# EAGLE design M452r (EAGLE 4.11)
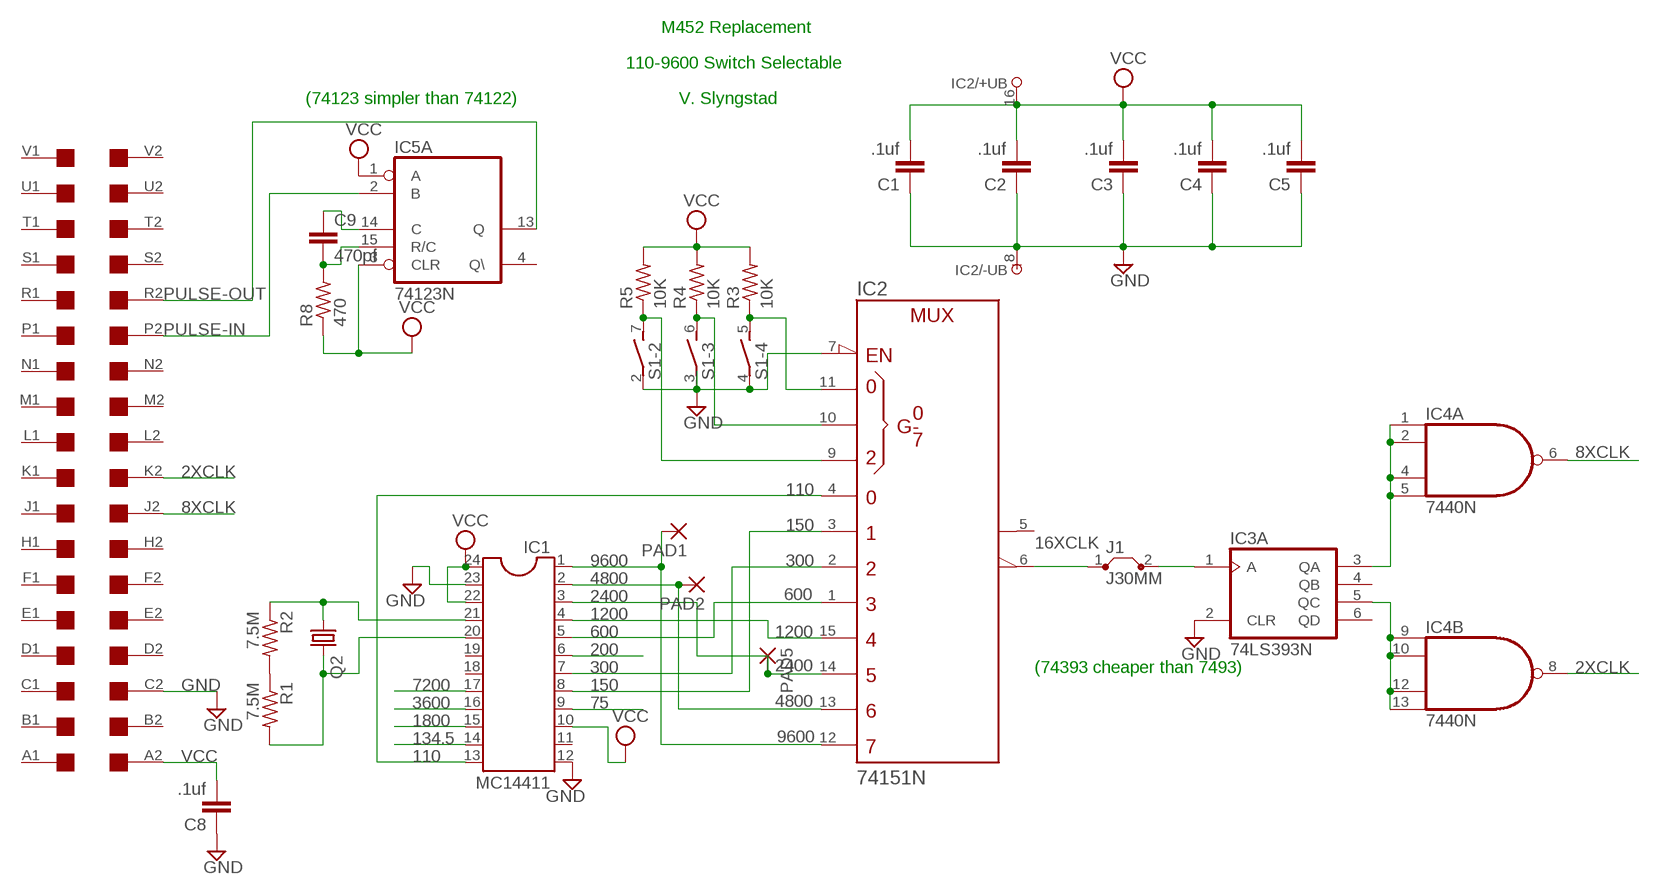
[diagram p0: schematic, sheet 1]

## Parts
C1  .1uf  C-EU050-025X075  [C050-025X075]
C2  .1uf  C-EU050-025X075  [C050-025X075]
C3  .1uf  C-EU050-025X075  [C050-025X075]
C4  .1uf  C-EU050-025X075  [C050-025X075]
C5  .1uf  C-EU050-025X075  [C050-025X075]
C8  .1uf  C-EU050-025X075  [C050-025X075]
C9  470pf  C-EU050-025X075  [C050-025X075]
IC1  MC14411  DIL24-6  [DIL24-6]
IC2  74151N  [DIL16]
IC3  74LS393N  [DIL14]
IC4  7440N  74S20N  [DIL14]
IC5  74123N  [DIL16]
J1  J30MM  [30]
PAD1  1,6/0,8  [1,6/0,8]
PAD2  1,6/0,8  [1,6/0,8]
PAD5  1,6/0,8  [1,6/0,8]
Q2  CRYTALHC49U-H  [HC49U-H]
R1  7.5M  R-US_0204/7  [0204/7]
R2  7.5M  R-US_0204/7  [0204/7]
R3  10K  R-US_0204/7  [0204/7]
R4  10K  R-US_0204/7  [0204/7]
R5  10K  R-US_0204/7  [0204/7]
R8  470  R-US_0204/7  [0204/7]
S1  DIP04S  [DIP04S]
U$1  DEC-FLIPCHIP  [DEC-FLIPCHIP]

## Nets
2XCLK: IC4.8(B:O) U$1.K2
8XCLK: IC4.6(A:O) U$1.J2
16XCLK: IC2.6(W) J1.1
75: IC1.9
110: IC1.13 IC2.4(D0)
134.5: IC1.14
150: IC1.8 IC2.3(D1)
200: IC1.6
300: IC1.7 IC2.2(D2)
600: IC1.5 IC2.1(D3)
1200: IC1.4 IC2.15(D4)
1800: IC1.15
2400: IC1.3 IC2.14(D5) PAD5.1(P)
3600: IC1.16
4800: IC1.2 IC2.13(D6) PAD2.1(P)
7200: IC1.17
9600: IC1.1 IC2.12(D7) PAD1.1(P)
GND: C1.1 C2.1 C3.1 C4.1 C5.1 C8.1 IC1.12 IC1.23 IC2.7(G\) IC2.8(-UB) IC3.2(A:CLR) S1.2 S1.3 S1.4 U$1.C2
N$1: IC1.20 Q2.2 R1.2
N$2: IC2.9(C) R5.1 S1.7
N$3: R1.1 R2.2
N$4: IC3.1(A:A) J1.2
N$10: IC3.5(A:QC) IC4.9(B:I0) IC4.10(B:I1) IC4.12(B:I2) IC4.13(B:I3)
N$12: IC3.3(A:QA) IC4.1(A:I0) IC4.2(A:I1) IC4.4(A:I2) IC4.5(A:I3)
N$17: IC2.11(A) R3.1 S1.5
N$18: IC1.21 Q2.1 R2.1
N$20: IC2.10(B) R4.1 S1.6
N$21: C9.2 IC5.15(A:R/C) R8.2
N$22: C9.1 IC5.14(A:C)
PULSE-IN: IC5.2(A:B) U$1.P2
PULSE-OUT: IC5.13(A:Q) U$1.R2
VCC: C1.2 C2.2 C3.2 C4.2 C5.2 C8.2 IC1.10 IC1.22 IC1.24 IC2.16(+UB) IC5.1(A:A) IC5.3(A:CLR) R3.2 R4.2 R5.2 R8.1 U$1.A2
Unconnected: IC1.11 IC1.18 IC1.19 IC2.5(Y) IC3.4(A:QB) IC3.6(A:QD) IC3.8(B:QD) IC3.9(B:QC) IC3.10(B:QB) IC3.11(B:QA) IC3.12(B:CLR) IC3.13(B:A) IC5.4(A:Q\) IC5.5(B:Q) IC5.6(B:C) IC5.7(B:R/C) IC5.9(B:A) IC5.10(B:B) IC5.11(B:CLR) IC5.12(B:Q\) S1.1 S1.8 U$1.A1 U$1.B1 U$1.B2 U$1.C1 U$1.D1 U$1.D2 U$1.E1 U$1.E2 U$1.F1 U$1.F2 U$1.H1 U$1.H2 U$1.J1 U$1.K1 U$1.L1 U$1.L2 U$1.M1 U$1.M2 U$1.N1 U$1.N2 U$1.P1 U$1.R1 U$1.S1 U$1.S2 U$1.T1 U$1.T2 U$1.U1 U$1.U2 U$1.V1 U$1.V2

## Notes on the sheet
- M452 Replacement
- 110-9600 Switch Selectable
- (74123 simpler than 74122) | V. Slyngstad
- (74393 cheaper than 7493)

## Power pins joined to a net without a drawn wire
GND: IC3.7(P:GND) IC4.7(P:GND) IC5.8(P:GND)
VCC: IC3.14(P:VCC) IC4.14(P:VCC) IC5.16(P:VCC)

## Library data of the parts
C1-C5 C8 C9 = rcl:C-EU: CAPACITOR, European symbol
IC1 = ic-package:DIL24: Dual In Line
IC2 = 74ttl-din:74*151: Data SELECTOR/MULTIPLEXER
IC3 = 74xx-us:74*393: Dual 4-bit decade and binary COUNTER
IC4 = 74xx-us:74*20: Dual 4-input NAND gate
IC5 = 74xx-us:74*123: Retriggerable monostable MULTIVIBRATOR
J1 = jumper:J: Bridge
PAD1 PAD2 PAD5 = wirepad:1,6/0,8: THROUGH-HOLE PAD
Q2 = crystal:CRYTAL: CRYSTAL
R1-R5 R8 = rcl:R-US_: RESISTOR, American symbol
S1 = switch-dil:DIP04S: DIL/CODE SWITCH
U$1 = con-dec:DEC-FLIPCHIP: DEC Flip-Chip single card fingers

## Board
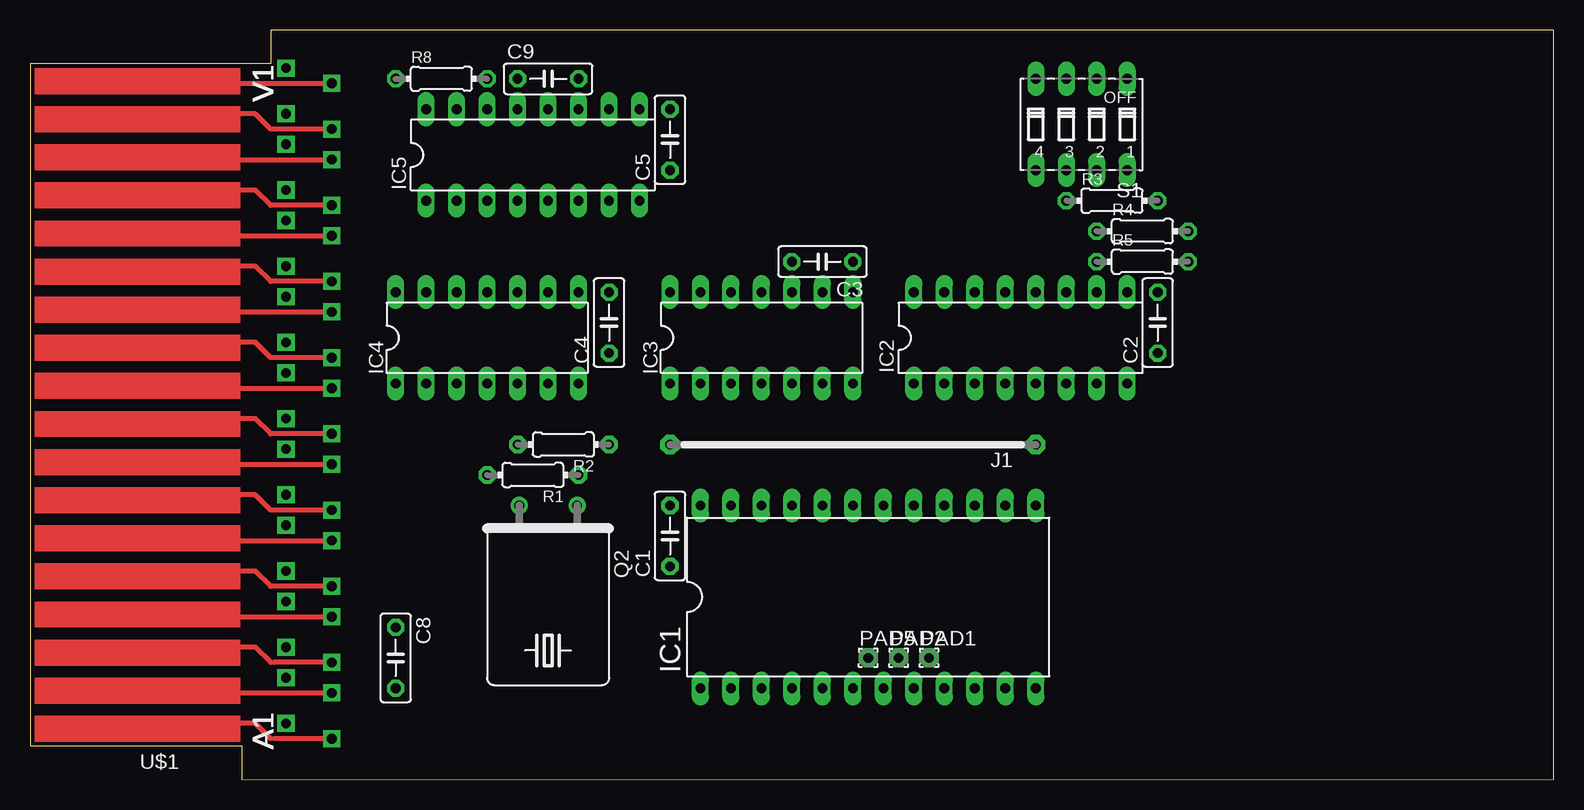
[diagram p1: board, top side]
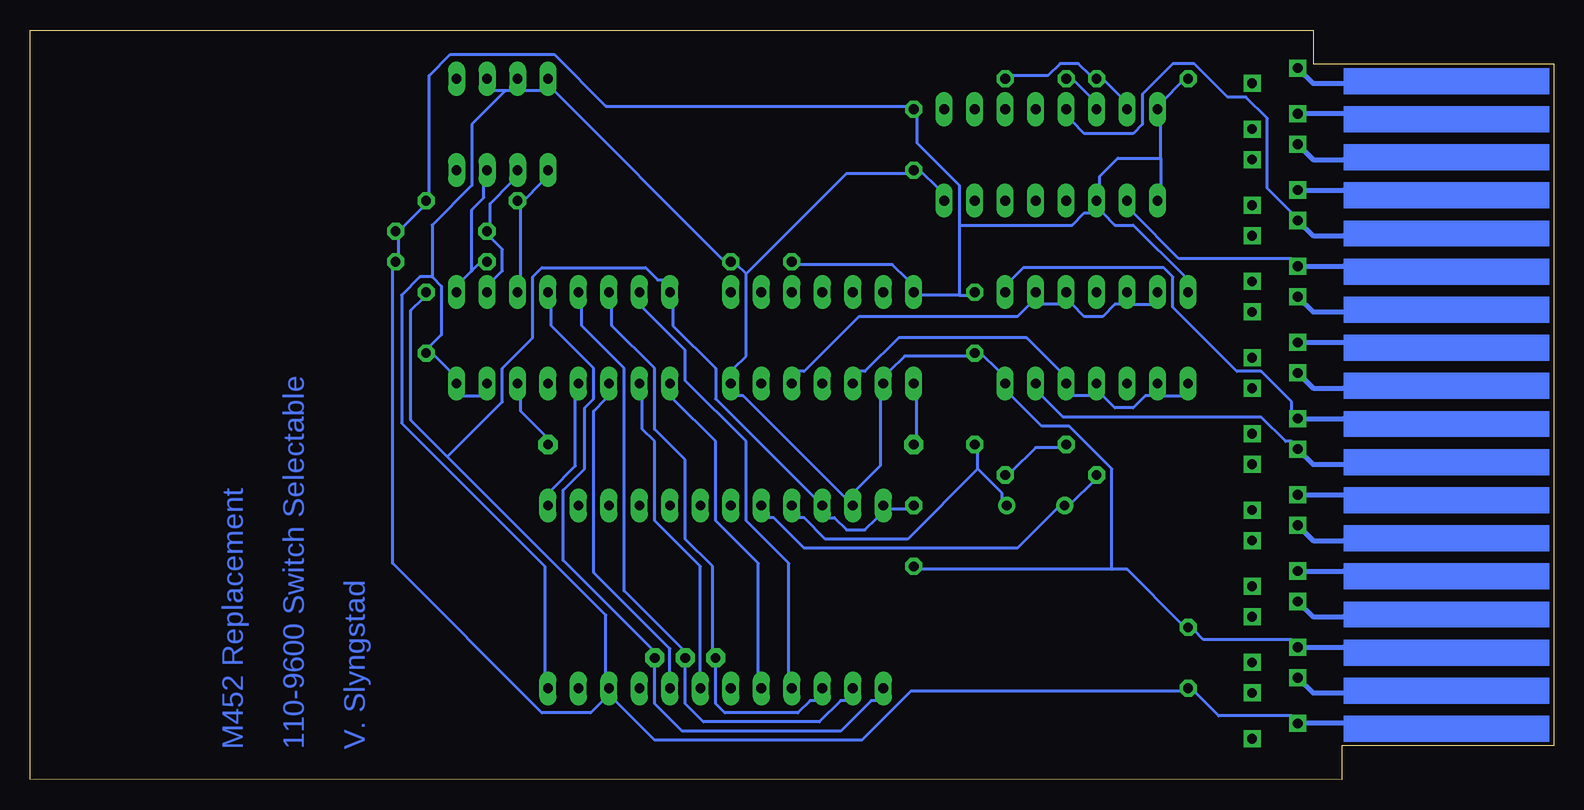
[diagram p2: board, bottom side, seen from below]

Size 126.98 x 62.48 mm. Coordinates in mm from the lower left corner, seen from the top.
Outline: 0,2.83 17.65,2.83 17.65,0 126.98,0.04 126.98,62.45 20.06,62.48 20.06,59.65 0,59.65 0,2.83
Copper layers (1*16): Top 0.035mm / dielectric 1.5mm / Bottom 0.035mm
Design rules "10mils": minimum track width 10mil, minimum drill 28mil, track to track 15mil, track to pad 10mil, pad to pad 10mil, via to via 10mil, smd to smd 10mil, copper to edge 40mil, drill to drill 10mil, minimum pad ring 12mil, minimum via ring 8mil, stop-mask expansion 0mil, vias tented up to drill 0mil, thermal gap 10mil

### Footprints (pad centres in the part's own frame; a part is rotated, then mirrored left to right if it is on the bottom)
C050-025X075 = drill 0.813 octagon: 1 -2.54,0; 2 2.54,0
DIL24-6 = drill 0.813 long: 1 -13.97,-7.62; 2 -11.43,-7.62; 3 -8.89,-7.62; 4 -6.35,-7.62; 5 -3.81,-7.62; 6 -1.27,-7.62; 7 1.27,-7.62; 8 3.81,-7.62; 9 6.35,-7.62; 10 8.89,-7.62; 11 11.43,-7.62; 12 13.97,-7.62; 13 13.97,7.62; 14 11.43,7.62; 15 8.89,7.62; 16 6.35,7.62; 17 3.81,7.62; 18 1.27,7.62; 19 -1.27,7.62; 20 -3.81,7.62; 21 -6.35,7.62; 22 -8.89,7.62; 23 -11.43,7.62; 24 -13.97,7.62
DIL16 = drill 0.813 long: 1 -8.89,-3.81; 2 -6.35,-3.81; 3 -3.81,-3.81; 4 -1.27,-3.81; 5 1.27,-3.81; 6 3.81,-3.81; 7 6.35,-3.81; 8 8.89,-3.81; 9 8.89,3.81; 10 6.35,3.81; 11 3.81,3.81; 12 1.27,3.81; 13 -1.27,3.81; 14 -3.81,3.81; 15 -6.35,3.81; 16 -8.89,3.81
DIL14 = drill 0.813 long: 1 -7.62,-3.81; 2 -5.08,-3.81; 3 -2.54,-3.81; 4 0,-3.81; 5 2.54,-3.81; 6 5.08,-3.81; 7 7.62,-3.81; 8 7.62,3.81; 9 5.08,3.81; 10 2.54,3.81; 11 0,3.81; 12 -2.54,3.81; 13 -5.08,3.81; 14 -7.62,3.81
30 = drill 0.813 pad 1.6 octagon: 1 -15.24,0; 2 15.24,0
1,6/0,8 = drill 0.813 pad 1.6 octagon: 1 0,0
HC49U-H = drill 0.813 round: 1 -2.413,-5.08; 2 2.413,-5.08
0204/7 = drill 0.813 octagon: 1 -3.81,0; 2 3.81,0
DIP04S = drill 0.813 long: 1 -3.81,-3.81; 2 -1.27,-3.81; 3 1.27,-3.81; 4 3.81,-3.81; 5 3.81,3.81; 6 1.27,3.81; 7 -1.27,3.81; 8 -3.81,3.81
DEC-FLIPCHIP = drill 0.813 square: A1 -7.62,27.94; A2 -3.81,26.67; B1 -7.62,24.13; B2 -3.81,22.86; C1 -7.62,21.59; C2 -3.81,20.32; D1 -7.62,17.78; D2 -3.81,16.51; E1 -7.62,15.24; E2 -3.81,13.97; F1 -7.62,11.43; F2 -3.81,10.16; H1 -7.62,8.89; H2 -3.81,7.62; J1 -7.62,5.08; J2 -3.81,3.81; K1 -7.62,2.54; K2 -3.81,1.27; L1 -7.62,-1.27; L2 -3.81,-2.54; M1 -7.62,-3.81; M2 -3.81,-5.08; N1 -7.62,-7.62; N2 -3.81,-8.89; P1 -7.62,-10.16; P2 -3.81,-11.43; R1 -7.62,-13.97; R2 -3.81,-15.24; S1 -7.62,-16.51; S2 -3.81,-17.78; T1 -7.62,-20.32; T2 -3.81,-21.59; U1 -7.62,-22.86; U2 -3.81,-24.13; V1 -7.62,-26.67; V2 -3.81,-27.94

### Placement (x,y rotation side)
C1  53.34,20.32 90 top
C2  93.98,38.1 90 top
C3  66.04,43.18 180 top
C4  48.25,38.1 90 top
C5  53.34,53.34 90 top
C8  30.48,10.16 270 top
C9  43.17,58.42 0 top
IC1  69.84,15.24 0 top
IC2  82.55,36.83 0 top
IC3  60.95,36.83 0 top
IC4  38.09,36.83 0 top
IC5  41.9,52.07 0 top
J1  68.58,27.94 180 top
PAD1  74.93,10.16 0 top
PAD2  72.39,10.16 0 top
PAD5  69.84,10.16 0 top
Q2  43.17,17.78 180 top
R1  41.9,25.4 180 top
R2  44.45,27.94 180 top
R3  90.17,48.26 0 top
R4  92.7,45.72 0 top
R5  92.7,43.18 0 top
R8  34.28,58.42 0 top
S1  87.62,54.61 180 top
U$1  17.52,31.37 180 top

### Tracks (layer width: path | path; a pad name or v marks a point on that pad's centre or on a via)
2XCLK
  Bottom 0.254: U$1.K2 21.84,30.73 21.84,31.5 24.38,34.04 26.41,34.04 31.75,39.37 31.75,41.91 32.51,42.67 44.19,42.67 45.21,41.66 IC4.8
8XCLK
  Bottom 0.254: U$1.J2 21.84,28.19 22.35,28.19 24.38,30.23 40.89,30.23 42.67,32 IC4.6
16XCLK
  Bottom 0.254: IC2.6 86.1,31.75 86.1,30.73 84.07,28.7 J1.1
110
  Bottom 0.254: IC2.4 81.53,31.75 81.53,26.16 83.56,24.13 IC1.13
150
  Bottom 0.254: IC1.8 73.66,10.92 80.01,17.27 80.01,30.73 78.99,31.75 IC2.3
300
  Bottom 0.254: IC1.7 71.12,17.78 74.93,21.59 74.93,28.19 75.94,29.21 75.94,31.75 IC2.2
600
  Bottom 0.254: IC1.5 66.29,8.89 66.29,18.03 69.84,21.59 69.84,28.19 73.4,31.75 IC2.1
1200
  Bottom 0.254: IC1.4 63.75,8.89 63.75,18.03 67.31,21.59 67.31,28.19 72.39,33.27 72.39,35.81 75.94,39.37 IC2.15
2400
  Bottom 0.254: IC1.3 61.46,6.6 61.97,6.6 62.99,5.59 69.08,5.59 69.84,6.35 PAD5.1 70.1,10.92 70.1,17.78 72.39,20.07 72.39,26.67 74.93,29.21 74.93,34.29 78.48,37.85 78.48,39.37 IC2.14
4800
  Bottom 0.254: IC2.13 81.02,39.37 81.02,37.85 77.47,34.29 77.47,15.75 72.64,10.92 PAD2.1 72.39,6.35 70.86,4.83 61.21,4.83 59.43,6.6 58.92,6.6 IC1.2
9600
  Bottom 0.254: IC1.1 56.38,6.6 56.89,6.6 59.43,4.06 72.64,4.06 74.93,6.35 PAD1.1 75.18,10.92 82.55,18.29 82.55,24.13 80.77,25.91 80.77,30.99 80.01,31.75 80.01,34.29 83.56,37.85 83.56,39.37 IC2.12
GND
  Bottom 0.254: IC2.7 89.4,32 90.93,32 IC2.8 91.94,34.04 93.47,35.56 C2.1 93.72,36.07 92.7,37.08 92.7,41.15 93.47,41.91 | 93.47,41.91 94.48,41.91 96.01,40.39 96.01,29.72 84.07,17.78 84.07,8.89 IC1.12 | U$1.C2 21.84,11.68 29.21,11.68 29.97,12.45 C8.1 30.98,12.95 35.55,17.53 36.82,17.53 | 36.82,17.53 52.83,17.53 C1.1 | 87.37,57.4 86.86,57.4 S1.3 85.85,57.4 84.32,57.4 S1.4 83.31,57.4 69.08,43.18 C3.1 68.07,42.93 67.31,42.16 | 87.37,57.4 88.39,57.4 S1.2 | IC5.8 51.3,49.28 52.83,50.8 C5.1 53.84,50.55 58.92,50.55 67.31,42.16 | 67.31,42.16 67.31,35.31 68.32,34.29 IC3.7 68.07,32 67.56,32 IC1.23 58.16,24.13 56.13,26.16 56.13,31.75 IC3.2 55.37,34.04 54.1,35.31 48.76,35.31 C4.1 47.75,35.56 46.22,34.04 IC4.7 45.21,32 42.67,29.46 40.38,29.46 36.82,25.91 36.82,17.53 | 93.47,41.91 93.47,46.23 90.17,49.53 90.17,54.61 87.37,57.4
N$1
  Bottom 0.254: R1.2 38.35,24.89 40.13,23.11 Q2.2 41.4,22.61 44.7,19.3 62.48,19.3 65.02,21.84 65.53,21.84 IC1.20
N$2
  Bottom 0.254: 90.17,42.42 89.4,43.18 R5.1 | 90.17,42.42 90.93,41.66 IC2.9 | 90.17,42.42 90.17,47.5 89.15,48.51 89.15,49.53 S1.7
N$3
  Bottom 0.254: R2.2 41.14,27.69 43.17,27.69 45.21,25.65 R1.1
N$4
  Bottom 0.254: IC3.1 53.08,31.75 53.08,28.7 J1.2
N$10
  Bottom 0.254: IC4.13 33.52,39.62 35.05,39.62 IC4.12 36.06,39.62 36.57,39.62 37.59,38.61 39.11,38.61 40.13,39.62 IC4.10 41.14,39.62 42.67,39.62 IC4.9 43.68,39.62 44.7,38.61 57.91,38.61 62.48,34.04 62.99,34.04 IC3.5
N$12
  Bottom 0.254: IC4.1 30.98,32 32.51,32 IC4.2 33.52,32 34.03,32 35.05,30.99 36.57,30.99 37.59,32 IC4.4 38.6,32 40.13,32 IC4.5 41.14,34.04 43.94,36.83 54.6,36.83 57.4,34.04 57.91,34.04 IC3.3
N$17
  Bottom 0.254: IC2.11 86.1,41.91 86.1,47.75 R3.1 85.85,48.26 84.32,49.78 S1.5
N$18
  Bottom 0.254: 48,25.91 45.97,23.88 45.97,23.37 Q2.1 | 48,25.91 48,27.43 R2.1 | 48,25.91 53.84,20.07 60.7,20.07 62.48,21.84 62.99,21.84 IC1.21
N$20
  Bottom 0.254: IC2.10 88.39,41.66 87.62,42.42 87.62,44.2 88.64,45.21 R4.1 88.64,46.23 88.64,48.01 86.86,49.78 S1.6
N$21
  Bottom 0.254: IC5.15 36.06,56.9 37.59,58.42 R8.2 38.6,58.67 39.62,59.69 41.14,59.69 42.16,58.67 45.21,58.67 C9.2
N$22
  Bottom 0.254: IC5.14 38.6,56.9 40.13,58.42 C9.1
PULSE-IN
  Bottom 0.254: U$1.P2 21.84,43.43 31.24,43.43 35.05,47.24 IC5.2
PULSE-OUT
  Bottom 0.254: U$1.R2 21.84,47.24 23.87,49.28 23.87,55.12 25.65,56.9 27.17,56.9 29.97,59.69 31.75,59.69 34.28,57.15 34.28,54.61 35.05,53.85 39.11,53.85 40.13,54.86 IC5.13
VCC
  Bottom 0.254: 32.76,51.82 32.76,54.61 IC5.16 32.51,56.64 30.98,58.17 R8.1 | 32.76,51.82 32.76,49.53 IC5.1 | IC4.14 30.73,41.91 35.05,46.23 36.57,46.23 37.59,47.24 IC5.3 | 32.76,51.82 36.32,51.82 37.84,50.29 37.84,49.53 IC5.3 | 49.52,40.39 52.83,40.39 IC3.14 53.84,41.66 55.11,42.93 62.99,42.93 C3.2 | 49.52,40.39 48.76,40.39 C4.2 | 49.52,46.23 49.52,40.39 | 49.52,46.23 49.52,49.53 53.08,53.09 53.08,55.37 C5.2 53.84,56.13 78.99,56.13 83.31,60.45 91.94,60.45 93.72,58.67 93.72,48.77 R3.2 94.23,47.75 96.01,45.97 R4.2 96.26,45.21 96.26,43.69 R5.2 96.77,42.67 96.77,18.03 84.32,5.59 80.26,5.59 79.24,6.6 IC1.10 | 49.52,46.23 40.13,46.23 39.11,47.24 38.6,47.24 IC5.3 | C1.2 53.84,22.61 55.37,22.61 IC1.24 56.38,21.84 57.4,20.83 58.92,20.83 59.94,21.84 60.45,21.84 IC1.22 69.84,31.75 69.84,34.29 73.4,37.85 73.4,39.37 IC2.16 74.16,41.66 74.67,41.66 75.69,42.67 84.32,42.67 85.09,41.91 85.09,36.83 87.62,34.29 87.62,31.5 92.2,26.92 | U$1.A2 21.84,5.33 27.94,5.33 29.97,7.37 C8.2 30.98,7.37 53.59,7.37 57.65,3.3 74.93,3.3 78.23,6.6 IC1.10 | 92.2,26.92 95.25,29.97 95.25,39.12 94.23,40.13 C2.2 | 92.2,26.92 78.99,13.72 78.99,8.89 IC1.10

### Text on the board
Bottom: V. Slyngstad | 110-9600 Switch Selectable | M452 Replacement
tNames: V1 | V1 | V1 | V1 | V1 | V1 | V1 | V1 | V1 | V1 | V1 | V1 | V1 | V1 | V1 | V1 | V1 | V1 | V1 | V1 | V1 | V1 | V1 | V1 | V1 | V1 | V1 | V1 | V1 | V1 | V1 | V1 | A1 | A1 | A1 | A1 | A1 | A1 | A1 | A1 | A1 | A1 | A1 | A1 | A1 | A1 | A1 | A1 | A1 | A1 | A1 | A1 | A1 | A1 | A1 | A1 | A1 | A1 | A1 | A1 | A1 | A1 | A1 | A1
